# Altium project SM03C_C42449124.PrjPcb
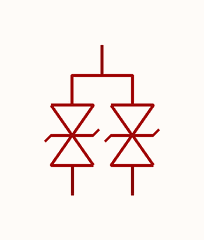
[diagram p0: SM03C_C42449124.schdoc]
1 sheet, 1 parts. Net scope: global (net labels, ports and power ports of the same name join across sheets).

## Sheet SM03C_C42449124.schdoc
size 127 x 101 mm

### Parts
D?  sm03c_c42449124  [SOT-23-3_L2.9-W1.3-P1.90-LS2.4-BR]  (value not drawn)

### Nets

Not connected (* = marked no-connect by the designer): D? 1 2 3

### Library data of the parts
D? = sm03c_c42449124: 极性:双向;反向截止电压(Vrwm):3.3V;钳位电压:16V；7.5V;峰值脉冲功率(Ppp):350W@8/20us;击穿电压(VBR):4V;; Manufacturer: JSMSEMI(杰盛微); ManufacturerPart: SM03C; AddInBom: yes; ModelId: c62791f0466c4ae2a892c056b845b0ca; ModelName: SOT-23-3P_L2.9-W1.3-H1.0-LS2.4-P0.95; ModelTransform: 98.425,114.173,0,180,0,0,0.0005,-0.0005,0; Polarity: 双向; Reverse Stand-Off Voltage (Vrwm): 3.3V; Voltage - Breakdown: 4V; Reverse Leakage Current (Ir): 40uA; Number of Channels: 双路; level of protection: IEC 61000-4-4；IEC 61000-4-2; Type: TVS; Junction Capacitance: 450pF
